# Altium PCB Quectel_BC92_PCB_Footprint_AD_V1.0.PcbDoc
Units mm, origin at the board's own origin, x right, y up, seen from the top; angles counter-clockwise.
Board outline 152.4 x 101.6 mm, 2 copper layers (Top Layer, Bottom Layer); 1 components, 0 nets, 50 pads, 0 vias.
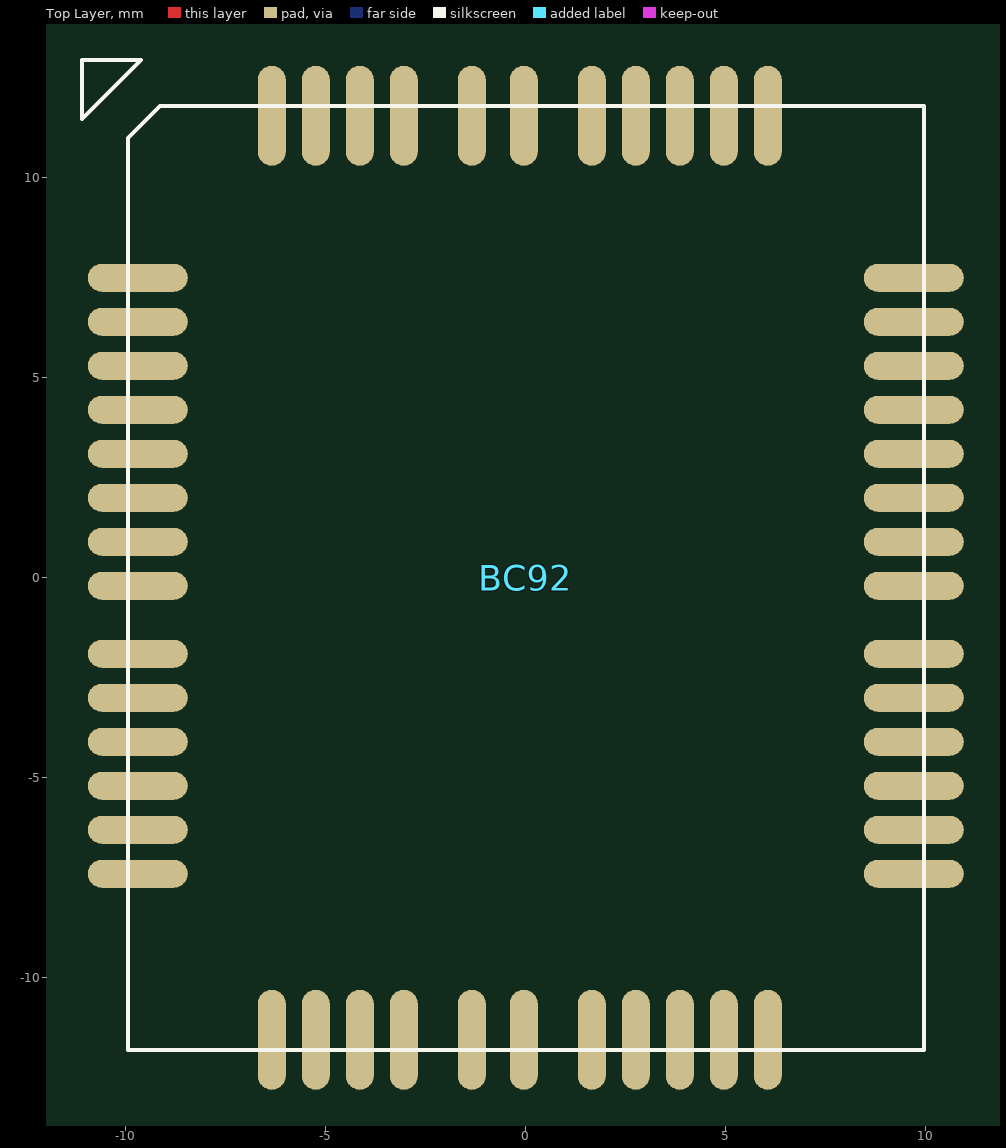
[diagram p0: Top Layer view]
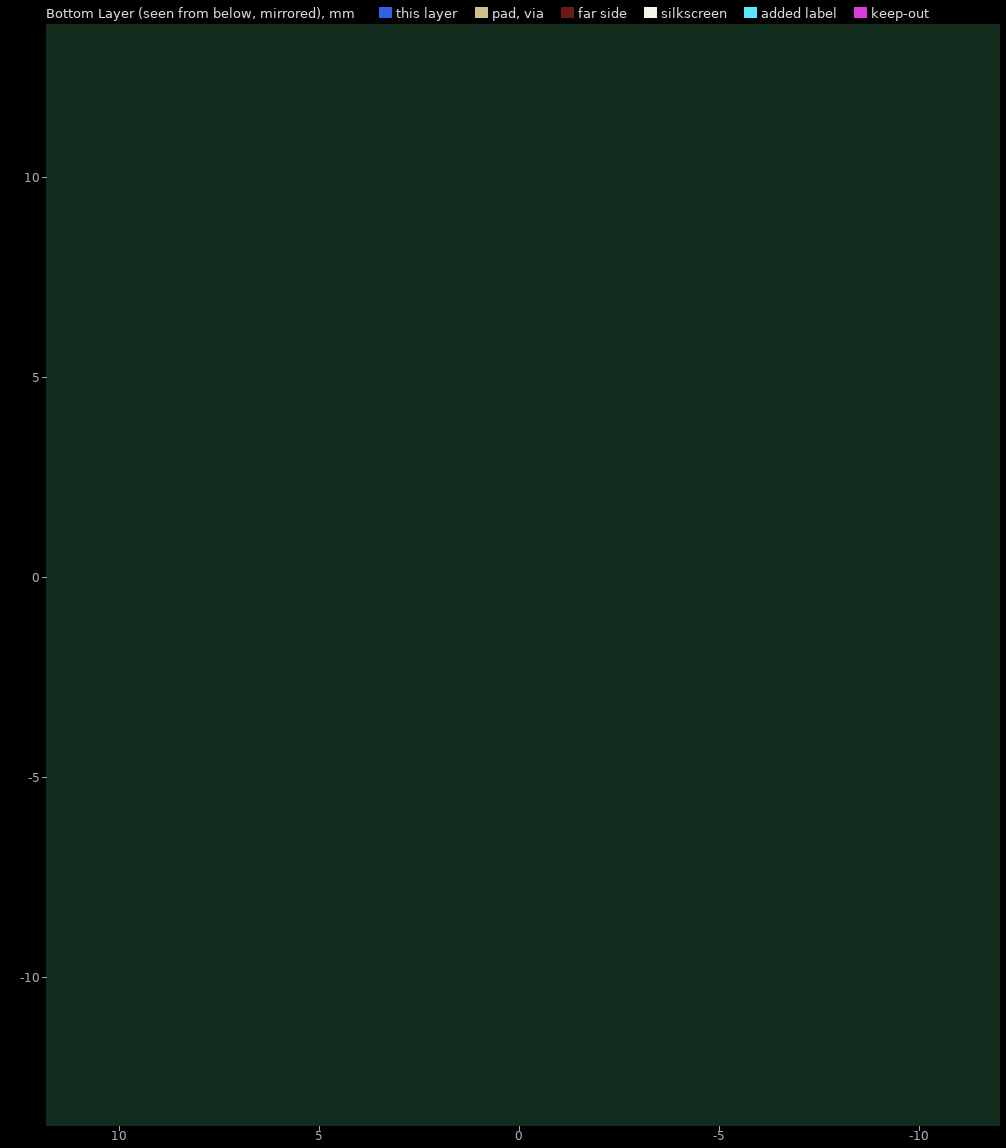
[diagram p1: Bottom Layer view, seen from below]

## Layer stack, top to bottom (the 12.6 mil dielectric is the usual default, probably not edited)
Top Layer: signal copper 0.0356
Dielectric: dielectric 0.32, FR-4, Dk 4.8
Bottom Layer: signal copper 0.0356

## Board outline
-60.96,-40.132 91.44,-40.132 91.44,61.468 -60.96,61.468

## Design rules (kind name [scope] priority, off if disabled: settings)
Clearance [All] p1: gap=0.254
PolygonConnect [All] p1: connectstyle=Relief reliefconductorwidth=0.254 reliefentries=4 polygonreliefangle="90 Angle" airgapwidth=0.254
RoutingVias [All] p1: holewidth=0.711 width=1.27 viastyle="Through Hole" minholewidth=0.711 minwidth=1.27 maxholewidth=0.711 maxwidth=1.27
SolderMaskExpansion [All] p1: expansion=0.102
Width [All] p1: maxlimit=0.254 minlimit=0.254 preferedwidth=0.254
28 further rules are at their usual default settings.

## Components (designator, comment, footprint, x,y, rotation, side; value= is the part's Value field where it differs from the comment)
BC92 "Comment" BC92 0,0 r0 top

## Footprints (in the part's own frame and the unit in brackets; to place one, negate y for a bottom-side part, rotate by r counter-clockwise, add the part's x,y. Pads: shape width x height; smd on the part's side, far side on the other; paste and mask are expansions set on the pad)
BC92 [mm] "NB-IoT Module BC92 23.6x19.9mm H2.2mm RO"
  oval 2.5x0.7 smd mask+0.05: 1(-9.7,7.5) 2(-9.7,6.4) 3(-9.7,5.3) 4(-9.7,4.2) 5(-9.7,3.1) 6(-9.7,-1.9) 7(-9.7,-3) 8(-9.7,-4.1) 9(-9.7,-5.2) 10(-9.7,-6.3) 11(-9.7,-7.4) 21(9.7,-7.4) 22(9.7,-6.3) 23(9.7,-5.2) 24(9.7,-4.1) 25(9.7,-3) 26(9.7,-1.9) 27(9.7,3.1) 28(9.7,4.2) 29(9.7,5.3) 30(9.7,6.4) 31(9.7,7.5) 43(9.7,-0.2) 44(9.7,0.9) 45(9.7,2) 48(-9.7,2) 49(-9.7,0.9) 50(-9.7,-0.2)
  oval 0.7x2.5 smd mask+0.05: 12(-6.35,-11.55) 13(-5.25,-11.55) 14(-4.15,-11.55) 15(-3.05,-11.55) 16(1.65,-11.55) 17(2.75,-11.55) 18(3.85,-11.55) 19(4.95,-11.55) 20(6.05,-11.55) 32(6.05,11.55) 33(4.95,11.55) 34(3.85,11.55) 35(2.75,11.55) 36(1.65,11.55) 37(-3.05,11.55) 38(-4.15,11.55) 39(-5.25,11.55) 40(-6.35,11.55) 41(-1.35,-11.55) 42(-0.05,-11.55) 46(-0.05,11.55) 47(-1.35,11.55)
  silkscreen extent -11.1,-11.8 9.95,12.95

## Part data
BC92: "NB-IoT Module BC92 23.6x19.9mm H2.2mm RO"

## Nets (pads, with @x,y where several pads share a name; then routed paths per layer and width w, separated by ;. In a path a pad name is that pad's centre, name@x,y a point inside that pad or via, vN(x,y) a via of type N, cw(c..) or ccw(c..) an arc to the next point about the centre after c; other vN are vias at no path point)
pads on no net: BC92.1 BC92.2 BC92.3 BC92.4 BC92.5 BC92.6 BC92.7 BC92.8 BC92.9 BC92.10 BC92.11 BC92.12 BC92.13 BC92.14 BC92.15 BC92.16 BC92.17 BC92.18 BC92.19 BC92.20 BC92.21 BC92.22 BC92.23 BC92.24 BC92.25 BC92.26 BC92.27 BC92.28 BC92.29 BC92.30 BC92.31 BC92.32 BC92.33 BC92.34 BC92.35 BC92.36 BC92.37 BC92.38 BC92.39 BC92.40 BC92.41 BC92.42 BC92.43 BC92.44 BC92.45 BC92.46 BC92.47 BC92.48 BC92.49 BC92.50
